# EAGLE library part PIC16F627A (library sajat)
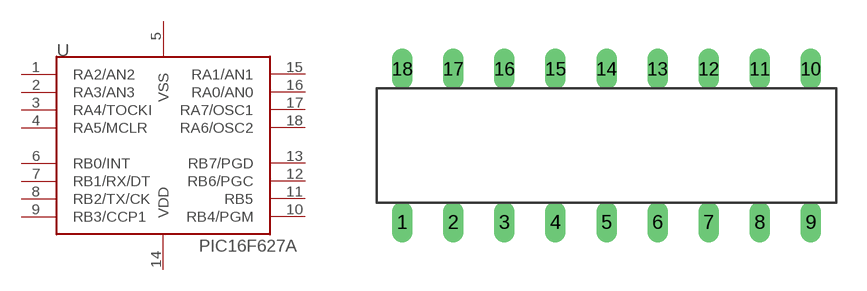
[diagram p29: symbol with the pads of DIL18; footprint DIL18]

Designator prefix -

## PIC16F627A  [DIL18]
1  RA2/AN2
2  RA3/AN3
3  RA4/TOCKI
4  RA5/MCLR
5  VSS
6  RB0/INT
7  RB1/RX/DT
8  RB2/TX/CK
9  RB3/CCP1
10  RB4/PGM
11  RB5
12  RB6/PGC
13  RB7/PGD
14  VDD
15  RA1/AN1
16  RA0/AN0
17  RA7/OSC1
18  RA6/OSC2

## Footprint DIL18 (pad centres in mm)
drill 0.3 pad 1.016 long: 1 -10.16,-3.81; 2 -7.62,-3.81; 3 -5.08,-3.81; 4 -2.54,-3.81; 5 0,-3.81; 6 2.54,-3.81; 7 5.08,-3.81; 8 7.62,-3.81; 9 10.16,-3.81; 10 10.16,3.81; 11 7.62,3.81; 12 5.08,3.81; 13 2.54,3.81; 14 0,3.81; 15 -2.54,3.81; 16 -5.08,3.81; 17 -7.62,3.81; 18 -10.16,3.81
